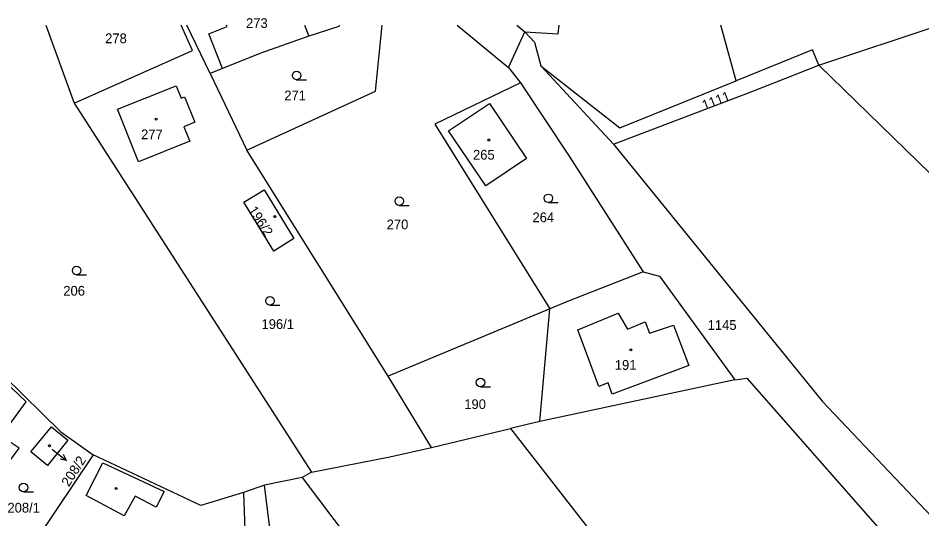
# Model space of a CAD drawing. Extents: x -520431 to -517205, y -1075927 to -1074013.
# Drawn here: x -517878.1 to -517719.9, y -1074101.2 to -1074013.6 of the extents above; entities that cross this region are included whole.
import ezdxf

# ---------------------------------------------------------------- set-up
doc = ezdxf.new("R2010")
doc.units = 0
for name, color, linetype in [('Hranice parcel', 7, 'Continuous'), ('Parcelní čísla', 7, 'Continuous'), ('Pop  PČ popisy', 7, 'Continuous'), ('Vnitřní kresba', 7, 'Continuous'), ('Značky budov', 7, 'Continuous'), ('Značky kultur', 7, 'Continuous')]:
    doc.layers.add(name, color=color, linetype=linetype)

msp = doc.modelspace()

# ---------------------------------------------------------------- linework, layer by layer
at = {"layer": 'Hranice parcel'}
for p, q in [((-517873.29, -1074014.78), (-517868.34, -1074028.42)), ((-517844.52, -1074023.23), (-517848.58, -1074014.78)), ((-517801.24, -1074014.78), (-517792.26, -1074022.22)), ((-517792.26, -1074022.22), (-517789.43, -1074015.98)), ((-517792.26, -1074022.22), (-517790.18, -1074024.91)), ((-517786.6, -1074021.91), (-517773.89, -1074035.64)), ((-517630.73, -1074126.27), (-517737.96, -1074021.78)), ((-517844.52, -1074023.23), (-517838.07, -1074036.64)), ((-517868.34, -1074028.42), (-517826.78, -1074093.02)), ((-517813.37, -1074076.24), (-517838.07, -1074036.64)), ((-517785.02, -1074064.45), (-517813.37, -1074076.24)), ((-517786.76, -1074084.15), (-517785.02, -1074064.45)), ((-517805.73, -1074088.69), (-517813.37, -1074076.24)), ((-517752.67, -1074076.88), (-517786.76, -1074084.15)), ((-517786.76, -1074084.15), (-517791.93, -1074085.38)), ((-517805.73, -1074088.69), (-517791.93, -1074085.38)), ((-517791.93, -1074085.38), (-517753.83, -1074134.19)), ((-517865.01, -1074089.97), (-517876.3, -1074106.78)), ((-517828.39, -1074093.96), (-517834.98, -1074095.28)), ((-517826.78, -1074093.02), (-517828.39, -1074093.96)), ((-517828.39, -1074093.96), (-517800.01, -1074131.48)), ((-517834.98, -1074095.28), (-517838.65, -1074096.55))]:
    msp.add_line(p, q, dxfattribs=at)
for points in [[(-517868.34, -1074028.42), (-517847.59, -1074019.2), (-517849.57, -1074014.78)], [(-517838.07, -1074036.64), (-517815.57, -1074026.35), (-517814.42, -1074014.78)], [(-517828, -1074014.78), (-517827.26, -1074016.71)], [(-517821.93, -1074014.78), (-517822, -1074015.01), (-517827.26, -1074016.71)], [(-517790.82, -1074014.78), (-517789.43, -1074015.98)], [(-517789.43, -1074015.98), (-517783.58, -1074016.32), (-517783.4, -1074014.78)], [(-517752.39, -1074024.51), (-517755.07, -1074014.78)], [(-517737.96, -1074021.78), (-517716.89, -1074014.78)], [(-517827.26, -1074016.71), (-517835.84, -1074019.74), (-517842.33, -1074022.35), (-517844.52, -1074023.23)], [(-517789.43, -1074015.98), (-517787.75, -1074017.78), (-517786.6, -1074021.91)], [(-517737.96, -1074021.78), (-517739.03, -1074019.1), (-517752.39, -1074024.51)], [(-517786.6, -1074021.91), (-517772.78, -1074032.73), (-517752.39, -1074024.51)], [(-517773.89, -1074035.64), (-517749.48, -1074026.37), (-517737.96, -1074021.78)], [(-517850.46, -1074025.42), (-517849.58, -1074027.57), (-517849.03, -1074027.34), (-517847.21, -1074031.77), (-517849.1, -1074032.56), (-517848.08, -1074035.09), (-517857.05, -1074038.71), (-517860.72, -1074029.52), (-517850.46, -1074025.42)], [(-517790.18, -1074024.91), (-517805.15, -1074032.12), (-517785.02, -1074064.45)], [(-517790.18, -1074024.91), (-517781.66, -1074037.72), (-517768.69, -1074057.95)], [(-517796.22, -1074042.88), (-517802.79, -1074033.28), (-517795.62, -1074028.51), (-517789.15, -1074038.12), (-517796.22, -1074042.88)], [(-517773.89, -1074035.64), (-517737.35, -1074080.57), (-517712.78, -1074106.51), (-517687.16, -1074128.23), (-517672.1, -1074136.12), (-517652.12, -1074134.92), (-517630.73, -1074126.27)], [(-517829.87, -1074052.15), (-517833.34, -1074054.33), (-517838.59, -1074045.79), (-517835.08, -1074043.58), (-517829.87, -1074052.15)], [(-517768.69, -1074057.95), (-517781.96, -1074063.17), (-517785.02, -1074064.45)], [(-517768.69, -1074057.95), (-517765.83, -1074058.73), (-517752.67, -1074076.88)], [(-517880.56, -1074076.24), (-517870.64, -1074085.96), (-517865.01, -1074089.97)], [(-517752.67, -1074076.88), (-517750.57, -1074076.55), (-517722.12, -1074108.88)], [(-517893.63, -1074093.8), (-517889.99, -1074090.26), (-517882.99, -1074095.54), (-517877.96, -1074088.82), (-517881.12, -1074086.71), (-517876.71, -1074080.7), (-517880.59, -1074077.04), (-517885.57, -1074083.7), (-517886.57, -1074082.94)], [(-517873.02, -1074091.82), (-517875.91, -1074089.46), (-517872.31, -1074085.07), (-517869.45, -1074087.42), (-517873.02, -1074091.82)], [(-517826.78, -1074093.02), (-517813.05, -1074090.35), (-517805.73, -1074088.69)], [(-517838.65, -1074096.55), (-517846.16, -1074098.85), (-517865.01, -1074089.97)], [(-517809.39, -1074139.37), (-517837.69, -1074106.22), (-517833.85, -1074104.7), (-517834.98, -1074095.28)], [(-517838.65, -1074096.55), (-517838.42, -1074103.16), (-517845.87, -1074109.71), (-517851.81, -1074117.06), (-517855.73, -1074113.81), (-517862.99, -1074119.85)]]:
    msp.add_lwpolyline(points, dxfattribs=at)
at = {"layer": 'Pop  PČ popisy'}
for p, q in [((-517872.16, -1074089.01), (-517872.05, -1074089.1)), ((-517872.05, -1074089.1), (-517869.68, -1074090.95)), ((-517869.68, -1074090.95), (-517870.78, -1074090.73)), ((-517869.68, -1074090.95), (-517870.17, -1074089.94))]:
    msp.add_line(p, q, dxfattribs=at)
at = {"layer": 'Vnitřní kresba'}
for p, q in [((-517844.76, -1074016.3), (-517841.54, -1074015.01)), ((-517841.54, -1074015.01), (-517841.63, -1074014.78)), ((-517842.33, -1074022.35), (-517844.76, -1074016.3)), ((-517780.16, -1074068.1), (-517773.1, -1074065.17)), ((-517773.1, -1074065.17), (-517771.43, -1074067.98)), ((-517771.43, -1074067.98), (-517768.34, -1074066.7)), ((-517768.34, -1074066.7), (-517767.56, -1074068.68)), ((-517767.56, -1074068.68), (-517763.41, -1074067.27)), ((-517763.41, -1074067.27), (-517760.68, -1074074.33)), ((-517776.43, -1074078.02), (-517780.16, -1074068.1)), ((-517760.68, -1074074.33), (-517774.12, -1074079.37)), ((-517774.84, -1074077.4), (-517776.43, -1074078.02)), ((-517774.12, -1074079.37), (-517774.84, -1074077.4)), ((-517866.21, -1074097.07), (-517863.32, -1074091.39)), ((-517863.32, -1074091.39), (-517852.54, -1074096.41)), ((-517859.58, -1074100.67), (-517866.21, -1074097.07)), ((-517857.67, -1074097.19), (-517859.58, -1074100.67)), ((-517853.98, -1074099.14), (-517857.67, -1074097.19)), ((-517852.54, -1074096.41), (-517853.98, -1074099.14))]:
    msp.add_line(p, q, dxfattribs=at)
at = {"layer": 'Značky budov'}
for centre in [(-517853.95, -1074031.26), (-517795.74, -1074034.89), (-517833.2, -1074048.3), (-517770.86, -1074071.59), (-517872.66, -1074088.38), (-517860.99, -1074095.87)]:
    msp.add_circle(centre, 0.175, dxfattribs=at)
at = {"layer": 'Značky kultur'}
for p, q in [((-517829.37, -1074024.33), (-517827.62, -1074024.33)), ((-517811.39, -1074046.34), (-517809.64, -1074046.34)), ((-517785.3, -1074045.84), (-517783.55, -1074045.84)), ((-517867.89, -1074058.47), (-517866.14, -1074058.47)), ((-517834.04, -1074063.78), (-517832.29, -1074063.78)), ((-517797.18, -1074078.06), (-517795.43, -1074078.06)), ((-517877.21, -1074096.43), (-517875.46, -1074096.43))]:
    msp.add_line(p, q, dxfattribs=at)
for centre in [(-517829.37, -1074023.58), (-517811.39, -1074045.59), (-517785.3, -1074045.09), (-517867.89, -1074057.72), (-517834.04, -1074063.03), (-517797.18, -1074077.31), (-517877.21, -1074095.68)]:
    msp.add_circle(centre, 0.75, dxfattribs=at)

# ---------------------------------------------------------------- texts
at = {"layer": 'Parcelní čísla'}
for s, p in [('273', (-517838.23, -1074015.28)), ('278', (-517862.9, -1074017.95)), ('271', (-517831.53, -1074027.94)), ('277', (-517856.6, -1074034.75)), ('265', (-517798.49, -1074038.32)), ('264', (-517788.08, -1074049.27)), ('270', (-517813.61, -1074050.51)), ('206', (-517870.23, -1074062.12)), ('196/1', (-517835.52, -1074067.95)), ('1145', (-517757.4, -1074068.11)), ('191', (-517773.66, -1074075.1)), ('190', (-517800.02, -1074081.96)), ('208/1', (-517880.01, -1074100.08))]:
    msp.add_text(s, height=1.7, dxfattribs=at).set_placement(p)
for s, rotation, p in [('1111', 21, (-517758, -1074029.69)), ('196/2', 303, (-517837.92, -1074047.14)), ('208/2', 57, (-517869.27, -1074095.67))]:
    msp.add_text(s, height=1.7, rotation=rotation, dxfattribs=at).set_placement(p)

doc.saveas('drawing.dxf')
